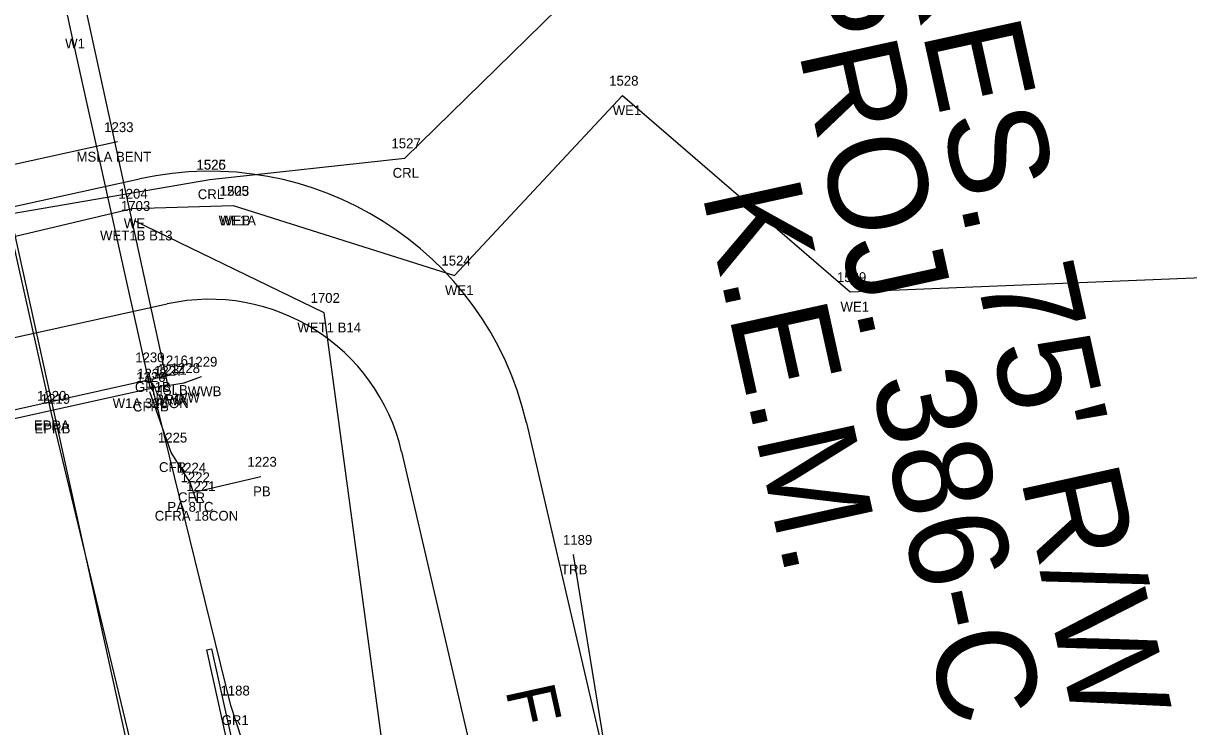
# Model space of a CAD drawing. Extents: x 2521558 to 2525396, y 882711 to 887632.
# Drawn here: x 2523806.5 to 2523924.8, y 885053.1 to 885124.5 of the extents above; entities that cross this region are included whole.
import ezdxf

# ---------------------------------------------------------------- set-up
doc = ezdxf.new("R2010")
doc.units = 0
for name, color, linetype in [('RD_EV_JurisArea', 7, 'Continuous'), ('RD_EX_BldgApp', 7, 'Continuous'), ('RD_EX_BldgApp_txCode', 7, 'Continuous'), ('RD_EX_Bridge', 7, 'Continuous'), ('RD_EX_Bridge_txCode', 7, 'Continuous'), ('RD_EX_Conc', 7, 'Continuous'), ('RD_EX_Conc_txCode', 7, 'Continuous'), ('RD_EX_DR_Pipe', 7, 'Continuous'), ('RD_EX_DR_Pipe_txCode', 7, 'Continuous'), ('RD_EX_GuardRail', 7, 'Continuous'), ('RD_EX_GuardRail_txCode', 7, 'Continuous'), ('RD_EX_H2O', 7, 'Continuous'), ('RD_EX_H2O_txCode', 7, 'Continuous'), ('RD_EX_H2O_WetLd_txCode', 7, 'Continuous'), ('RD_EX_Misc', 7, 'Continuous'), ('RD_EX_Misc_txCode', 7, 'Continuous'), ('RD_EX_Road', 7, 'Continuous'), ('RD_EX_Road_txCode', 7, 'Continuous'), ('RD_EX_RW_TX', 7, 'Continuous'), ('RD_EX_VEG', 7, 'Continuous'), ('RD_EX_VEG_txCode', 7, 'Continuous'), ('RD_PD_Bridge', 7, 'Continuous'), ('RD_PD_CstnLmt', 7, 'Continuous'), ('RD_PD_DR_ErosCtrl', 7, 'Continuous'), ('RD_PD_Final_TrvlWay', 7, 'Continuous'), ('RD_PD_GR', 7, 'Continuous'), ('RD_SMD_Locator', 7, 'Continuous')]:
    doc.layers.add(name, color=color, linetype=linetype)

# ---------------------------------------------------------------- blocks, each defined once
blk = doc.blocks.new('TBC1')
at = {"layer": 'RD_PD_GR'}
blk.add_lwpolyline([(12.5, 2.5), (15, 2.5), (15, 0.49), (25, 0.49), (25, 2.5), (27.5, 2.5), (27.5, 0.49), (31.25, 0.49), (31.25, 0), (0, 0), (0, 0.49), (12.5, 0.49)], close=True, dxfattribs=at)

msp = doc.modelspace()

# ---------------------------------------------------------------- linework, layer by layer
at = {"layer": 'RD_EV_JurisArea'}
msp.add_lwpolyline([(2523944.86, 884550.08), (2523910.41, 884709.58), (2523888.01, 884815.03), (2523863.93, 884918.37), (2523848.43, 885010.84), (2523837.07, 885095.13), (2523817.82, 885104.47)], dxfattribs=at)
at = {"layer": 'RD_EX_BldgApp'}
msp.add_lwpolyline([(2523819.44, 885087.44), (2523811.32, 885123.96), (2523803.31, 885161.5)], dxfattribs=at)
at = {"layer": 'RD_EX_Bridge'}
for points in [[(2523774.91, 885077.6), (2523821.2, 885087.83), (2523805.06, 885161.89), (2523758.15, 885151.44), (2523774.91, 885077.6)], [(2523821.15, 885087.73), (2523822.84, 885088), (2523824.6, 885088.65)]]:
    msp.add_lwpolyline(points, dxfattribs=at)
at = {"layer": 'RD_EX_Conc'}
msp.add_lwpolyline([(2523824.12, 885076.01), (2523823.45, 885077.89), (2523821.53, 885080.95), (2523819.36, 885087.1)], dxfattribs=at)
at = {"layer": 'RD_EX_DR_Pipe'}
msp.add_line((2523823.84, 885076.92), (2523830.63, 885078.49), dxfattribs=at)
at = {"layer": 'RD_EX_GuardRail'}
msp.add_lwpolyline([(2523841.11, 885013.81), (2523827.6, 885055.26), (2523819.28, 885089.09)], dxfattribs=at)
at = {"layer": 'RD_EX_H2O'}
for points in [[(2523582.82, 884766.34), (2523598.11, 884856.98), (2523627.59, 884901.75), (2523623.76, 884928.28), (2523586.58, 884955.43), (2523600.94, 884974.12), (2523633.05, 884997.68), (2523679.17, 885037.05), (2523744.72, 885076.89), (2523769.38, 885099), (2523825.47, 885108.66), (2523825.47, 885108.66), (2523845.24, 885110.83), (2523890.25, 885154.93)], [(2523827.83, 885106), (2523850.3, 885098.92), (2523867.33, 885117.19), (2523890.44, 885097.24), (2523927.79, 885098.78), (2523966.35, 885109.5), (2523978.17, 885083.37)], [(2523792.73, 884941.12), (2523763.67, 885051.56), (2523756.26, 885062.72), (2523770.47, 885094.55), (2523817.57, 885105.71), (2523827.83, 885106)]]:
    msp.add_lwpolyline(points, dxfattribs=at)
at = {"layer": 'RD_EX_Misc'}
for p, q in [((2523816.08, 885112.47), (2523769.2, 885102.22)), ((2523774.43, 885078.31), (2523821.35, 885088.78))]:
    msp.add_line(p, q, dxfattribs=at)
at = {"layer": 'RD_EX_Road'}
for p, q in [((2523809.32, 885085.19), (2523803.79, 885109.94)), ((2523809.38, 885084.88), (2523809.32, 885085.19)), ((2523817.58, 885050.92), (2523809.38, 885084.88))]:
    msp.add_line(p, q, dxfattribs=at)
at = {"layer": 'RD_EX_VEG'}
msp.add_lwpolyline([(2523998.75, 884575.96), (2523966.17, 884559.06), (2523924.93, 884771.45), (2523880.33, 884960.16), (2523862.36, 885070.56)], dxfattribs=at)
at = {"layer": 'RD_PD_CstnLmt'}
msp.add_line((2523844.92, 885081.02), (2523855.75, 885034.37), dxfattribs=at)
msp.add_lwpolyline([(2523770.59, 885084.9), (2523821.14, 885096.03)], dxfattribs=at)
msp.add_arc((2523825.44, 885076.49), 20, 13.0724, 102.4185, dxfattribs=at)
at = {"layer": 'RD_PD_DR_ErosCtrl'}
msp.add_line((2523857.58, 885083.96), (2523868.41, 885037.31), dxfattribs=at)
msp.add_lwpolyline([(2523767.8, 885097.59), (2523818.34, 885108.72)], dxfattribs=at)
msp.add_arc((2523825.44, 885076.49), 33, 13.0724, 102.4185, dxfattribs=at)
at = {"layer": 'RD_PD_Final_TrvlWay'}
msp.add_line((2523720.24, 885490.91), (2524037.44, 884050.42), dxfattribs=at)
at = {"layer": 'RD_SMD_Locator'}
for centre in [(2523811.32, 885123.96), (2523867.33, 885117.19), (2523816.08, 885112.47), (2523845.24, 885110.83), (2523825.47, 885108.66), (2523825.47, 885108.66), (2523827.83, 885106), (2523827.83, 885106), (2523817.57, 885105.71), (2523817.82, 885104.47), (2523850.3, 885098.92), (2523890.44, 885097.24), (2523837.07, 885095.13), (2523819.28, 885089.09), (2523821.35, 885088.78), (2523824.6, 885088.65), (2523819.36, 885087.1), (2523819.44, 885087.44), (2523821.15, 885087.73), (2523821.2, 885087.83), (2523822.84, 885088), (2523809.32, 885085.19), (2523809.38, 885084.88), (2523821.53, 885080.95), (2523823.45, 885077.89), (2523830.63, 885078.49), (2523823.84, 885076.92), (2523824.12, 885076.01), (2523862.36, 885070.56), (2523827.6, 885055.26)]:
    msp.add_circle(centre, 0.001, dxfattribs=at)

# ---------------------------------------------------------------- block references
at = {"layer": 'RD_PD_Bridge', "rotation": -77.58151740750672}
msp.add_blockref('TBC1', (2523825.16, 885060.91), dxfattribs=at)

# ---------------------------------------------------------------- texts
at = {"layer": 'RD_EX_BldgApp_txCode'}
for s, p in [('W1', (2523810.78, 885121.96)), ('1232', (2523818.09, 885088.44)), ('W1A 32CON', (2523815.6, 885085.44))]:
    msp.add_text(s, height=1, dxfattribs=at).set_placement(p)
at = {"layer": 'RD_EX_Bridge_txCode'}
for s, p in [('1229', (2523823.25, 885089.65)), ('1227', (2523819.8, 885088.73)), ('1231', (2523820.13, 885088.83)), ('1228', (2523821.49, 885089)), ('WW', (2523821.93, 885086)), ('WWB', (2523823.22, 885086.65)), ('WWA', (2523819.75, 885085.73)), ('BRC', (2523819.95, 885085.83))]:
    msp.add_text(s, height=1, dxfattribs=at).set_placement(p)
at = {"layer": 'RD_EX_Conc_txCode'}
for s, p in [('1226', (2523817.99, 885088.1)), ('CFRB', (2523817.66, 885085.1)), ('1225', (2523820.19, 885081.95)), ('CFR', (2523820.3, 885078.95)), ('1224', (2523822.11, 885078.89)), ('1221', (2523823.06, 885077.01)), ('CFR', (2523822.23, 885075.89)), ('CFRA 18CON', (2523819.87, 885074.01))]:
    msp.add_text(s, height=1, dxfattribs=at).set_placement(p)
at = {"layer": 'RD_EX_DR_Pipe_txCode'}
for s, p in [('1223', (2523829.28, 885079.49)), ('1222', (2523822.49, 885077.92)), ('PB', (2523829.85, 885076.49)), ('PA 8TC', (2523821.15, 885074.92))]:
    msp.add_text(s, height=1, dxfattribs=at).set_placement(p)
at = {"layer": 'RD_EX_GuardRail_txCode'}
for s, p in [('1230', (2523817.89, 885090.09)), ('GR1B', (2523817.86, 885087.09)), ('1188', (2523826.54, 885056.26)), ('GR1', (2523826.66, 885053.26))]:
    msp.add_text(s, height=1, dxfattribs=at).set_placement(p)
at = {"layer": 'RD_EX_H2O_txCode'}
for s, p in [('1528', (2523865.98, 885118.19)), ('WE1', (2523866.34, 885115.19)), ('1527', (2523843.89, 885111.83)), ('1526', (2523824.1, 885109.66)), ('1525', (2523824.12, 885109.66)), ('CRL', (2523844.01, 885108.83)), ('1204', (2523816.18, 885106.71)), ('CRL', (2523824.24, 885106.66)), ('CRL', (2523824.24, 885106.66)), ('1205', (2523826.44, 885107)), ('1523', (2523826.48, 885107)), ('WE', (2523816.73, 885103.71)), ('WE1A', (2523826.35, 885104)), ('WEB', (2523826.53, 885104)), ('1524', (2523848.96, 885099.92)), ('1529', (2523889.09, 885098.24)), ('WE1', (2523849.32, 885096.92)), ('WE1', (2523889.45, 885095.24))]:
    msp.add_text(s, height=1, dxfattribs=at).set_placement(p)
at = {"layer": 'RD_EX_H2O_WetLd_txCode'}
for s, p in [('1703', (2523816.44, 885105.47)), ('WET1B B13', (2523814.32, 885102.47)), ('1702', (2523835.68, 885096.13)), ('WET1 B14', (2523834.34, 885093.13))]:
    msp.add_text(s, height=1, dxfattribs=at).set_placement(p)
at = {"layer": 'RD_EX_Misc_txCode'}
for s, p in [('1233', (2523814.74, 885113.47)), ('MSLA BENT', (2523811.93, 885110.47)), ('1216', (2523820.26, 885089.78)), ('MSLB', (2523819.58, 885086.78))]:
    msp.add_text(s, height=1, dxfattribs=at).set_placement(p)
at = {"layer": 'RD_EX_Road_txCode'}
for s, p in [('1220', (2523807.93, 885086.19)), ('1219', (2523808.31, 885085.88)), ('EPRA', (2523807.6, 885083.19)), ('EPRB', (2523807.67, 885082.88))]:
    msp.add_text(s, height=1, dxfattribs=at).set_placement(p)
at = {"layer": 'RD_EX_RW_TX'}
for s, p in [("PRES. 75' R/W ", (2523893.73, 885141.81)), ('PROJ. 386-C ', (2523883.26, 885130.4)), ('K.E.M.', (2523875.37, 885107.29))]:
    msp.add_text(s, height=10, rotation=282.4185, dxfattribs=at).set_placement(p)
at = {"layer": 'RD_EX_VEG_txCode'}
for s, p in [('1189', (2523861.29, 885071.56)), ('TRB', (2523861.09, 885068.56))]:
    msp.add_text(s, height=1, dxfattribs=at).set_placement(p)
at = {"layer": 'RD_PD_CstnLmt'}
msp.add_text("F 46'", height=5, rotation=282.4185, dxfattribs=at).set_placement((2523855.43, 885056.8))

doc.saveas('drawing.dxf')
